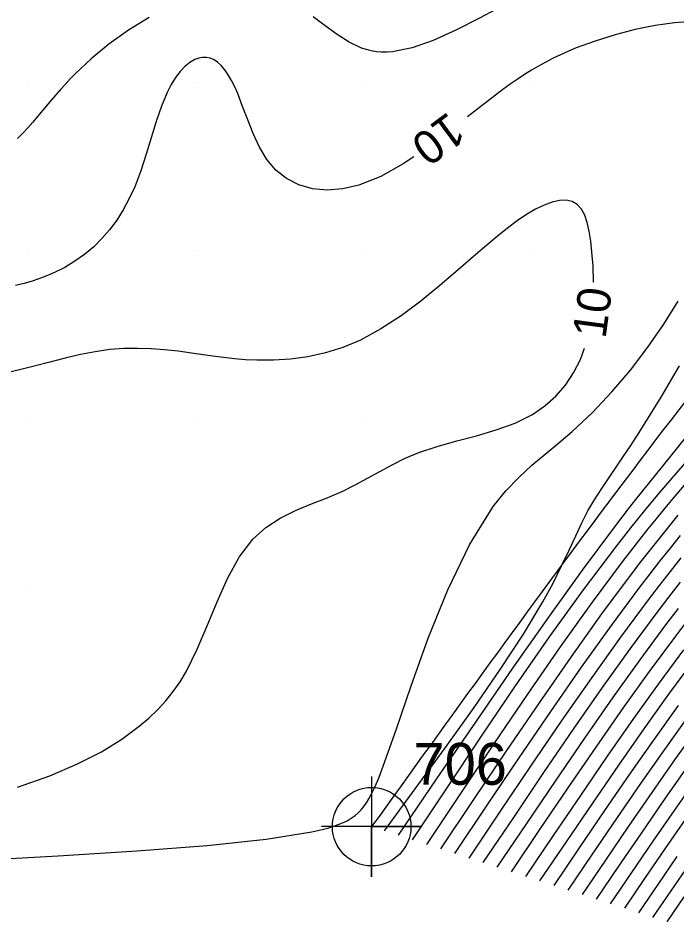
# Model space of a CAD drawing. Extents: x 2602990 to 2605851, y 618069 to 619180.
# Drawn here: x 2603719.5 to 2603758.8, y 618249.9 to 618303.9 of the extents above; entities that cross this region are included whole.
import ezdxf

# ---------------------------------------------------------------- set-up
doc = ezdxf.new("R2010")
doc.units = 0
for name, color, linetype in [('DTM Contours Major', 7, 'Continuous'), ('DTM Contours Major Text', 7, 'Continuous'), ('DTM Contours Minor', 7, 'Continuous'), ('DTM Contours Minor Text', 7, 'Continuous'), ('Exist DTM Breakline', 7, 'Continuous'), ('Exist DTM Breakline Cogo Number', 7, 'Continuous'), ('Exist DTM Breakline Cogo Point CELL', 7, 'Continuous'), ('Exist DTM QL2 LIDAR Elevation Point', 7, 'Continuous')]:
    doc.layers.add(name, color=color, linetype=linetype)

# ---------------------------------------------------------------- blocks, each defined once
blk = doc.blocks.new('EXIST DTM BREAKLINE COGO POINT')
at = {"layer": 'Exist DTM Breakline Cogo Point CELL'}
blk.add_lwpolyline([(0, 0.06), (0, -0.06), (0, 0), (0.06, 0), (-0.06, 0)], dxfattribs=at)
blk.add_circle((0, 0), 0.0469, dxfattribs=at)

msp = doc.modelspace()

# ---------------------------------------------------------------- linework, layer by layer
at = {"layer": 'DTM Contours Major'}
for points in [[(2603759.732, 618303.667), (2603758.66, 618303.592), (2603757.512, 618303.427), (2603756.32, 618303.182), (2603755.116, 618302.87), (2603753.933, 618302.5), (2603752.804, 618302.084), (2603752.329, 618301.887), (2603751.868, 618301.682), (2603751.42, 618301.468), (2603750.982, 618301.243), (2603750.552, 618301.007), (2603750.128, 618300.758), (2603749.703, 618300.492), (2603749.278, 618300.211), (2603748.852, 618299.916), (2603748.42, 618299.604), (2603747.981, 618299.276), (2603747.53, 618298.93), (2603746.308, 618297.971)], [(2603743.099, 618295.586), (2603742.455, 618295.156), (2603741.126, 618294.418), (2603739.815, 618293.891), (2603738.848, 618293.667), (2603737.917, 618293.598), (2603737.038, 618293.68), (2603736.225, 618293.908), (2603735.493, 618294.28), (2603734.855, 618294.792), (2603734.323, 618295.431), (2603733.88, 618296.169), (2603733.504, 618296.968), (2603733.176, 618297.79), (2603732.874, 618298.599), (2603732.578, 618299.357), (2603732.397, 618299.77), (2603732.209, 618300.149), (2603732.014, 618300.488), (2603731.811, 618300.786), (2603731.599, 618301.037), (2603731.376, 618301.238), (2603731.162, 618301.376), (2603730.941, 618301.469), (2603730.713, 618301.517), (2603730.481, 618301.521), (2603730.246, 618301.48), (2603730.01, 618301.394), (2603729.713, 618301.224), (2603729.42, 618300.987), (2603729.135, 618300.686), (2603728.861, 618300.324), (2603728.6, 618299.905), (2603728.357, 618299.43), (2603728.021, 618298.611), (2603727.714, 618297.703), (2603727.119, 618295.741), (2603726.793, 618294.748), (2603726.426, 618293.789), (2603726.103, 618293.088), (2603725.744, 618292.427), (2603725.352, 618291.807), (2603724.926, 618291.23), (2603724.467, 618290.697), (2603723.977, 618290.21), (2603723.433, 618289.753), (2603722.858, 618289.345), (2603722.255, 618288.984), (2603721.628, 618288.669), (2603720.977, 618288.398), (2603720.308, 618288.168), (2603719.815, 618288.027), (2603719.312, 618287.904)], [(2603716.836, 618253.558), (2603721.856, 618253.833), (2603726.546, 618254.132), (2603730.744, 618254.463), (2603734.284, 618254.839), (2603737.002, 618255.271), (2603737.371, 618255.351), (2603737.712, 618255.434), (2603738.028, 618255.519), (2603738.319, 618255.609), (2603738.587, 618255.703), (2603738.833, 618255.803), (2603738.976, 618255.868), (2603739.112, 618255.937), (2603739.241, 618256.008), (2603739.363, 618256.082), (2603739.479, 618256.16), (2603739.588, 618256.241), (2603739.779, 618256.404), (2603739.954, 618256.583), (2603740.116, 618256.78), (2603740.268, 618256.997), (2603740.414, 618257.236), (2603740.556, 618257.498), (2603740.672, 618257.732), (2603740.788, 618257.983), (2603740.905, 618258.254), (2603741.024, 618258.544), (2603741.272, 618259.187), (2603742.036, 618261.359), (2603742.933, 618263.981), (2603743.963, 618266.84), (2603745.124, 618269.723), (2603746.418, 618272.416), (2603747.843, 618274.706), (2603748.59, 618275.628), (2603749.363, 618276.435), (2603750.152, 618277.16), (2603750.953, 618277.836), (2603751.757, 618278.497), (2603752.557, 618279.177), (2603753.765, 618280.312), (2603754.933, 618281.545), (2603756.045, 618282.851), (2603757.085, 618284.207), (2603758.037, 618285.587), (2603758.885, 618286.967)], [(2603748.927, 618252.885), (2603750.631, 618255.411), (2603752.321, 618257.904), (2603753.985, 618260.331), (2603755.608, 618262.658), (2603757.177, 618264.854), (2603758.679, 618266.885), (2603759.469, 618267.917)], [(2603762.47, 618257.475), (2603761.761, 618256.5), (2603760.646, 618254.929), (2603759.544, 618253.346), (2603758.45, 618251.756), (2603757.361, 618250.163)]]:
    msp.add_lwpolyline(points, dxfattribs=at)
at = {"layer": 'DTM Contours Minor'}
for points in [[(2603749.955, 618305.441), (2603747.028, 618303.861), (2603745.615, 618303.141), (2603744.263, 618302.534), (2603742.992, 618302.089), (2603741.823, 618301.857), (2603741.492, 618301.836), (2603741.172, 618301.838), (2603740.861, 618301.864), (2603740.558, 618301.914), (2603740.263, 618301.986), (2603739.973, 618302.081), (2603739.237, 618302.431), (2603738.52, 618302.89), (2603737.807, 618303.413), (2603737.08, 618303.952)], [(2603727.281, 618303.9), (2603726.05, 618303.142), (2603724.889, 618302.308), (2603723.826, 618301.435), (2603722.888, 618300.559), (2603722.57, 618300.233), (2603722.271, 618299.911), (2603721.988, 618299.595), (2603721.459, 618298.979), (2603720.624, 618297.986), (2603720.334, 618297.65), (2603720.041, 618297.321), (2603719.741, 618296.999), (2603719.43, 618296.682)], [(2603753.835, 618288.103), (2603753.835, 618288.124), (2603753.803, 618289.048), (2603753.737, 618289.918), (2603753.666, 618290.556), (2603753.576, 618291.139), (2603753.457, 618291.657), (2603753.304, 618292.102), (2603753.108, 618292.466), (2603752.862, 618292.737), (2603752.559, 618292.912), (2603752.204, 618292.991), (2603751.802, 618292.979), (2603751.359, 618292.882), (2603750.88, 618292.705), (2603750.372, 618292.455), (2603749.836, 618292.135), (2603749.276, 618291.753), (2603748.691, 618291.316), (2603748.083, 618290.831), (2603747.451, 618290.304), (2603746.796, 618289.743), (2603745.746, 618288.832), (2603744.647, 618287.894), (2603743.507, 618286.968), (2603742.333, 618286.091), (2603741.132, 618285.303), (2603739.909, 618284.641), (2603738.862, 618284.203), (2603737.813, 618283.873), (2603736.768, 618283.642), (2603735.734, 618283.498), (2603734.718, 618283.432), (2603733.729, 618283.433), (2603733.052, 618283.468), (2603732.389, 618283.525), (2603731.736, 618283.599), (2603731.09, 618283.684), (2603729.808, 618283.866), (2603729.013, 618283.969), (2603728.214, 618284.056), (2603727.41, 618284.118), (2603726.599, 618284.146), (2603725.779, 618284.133), (2603724.949, 618284.07), (2603724.071, 618283.947), (2603723.179, 618283.773), (2603722.273, 618283.563), (2603721.353, 618283.328), (2603720.416, 618283.083), (2603719.463, 618282.839), (2603718.251, 618282.555)], [(2603719.425, 618257.932), (2603721.356, 618258.617), (2603723.015, 618259.326), (2603724.435, 618260.056), (2603725.649, 618260.806), (2603726.691, 618261.573), (2603727.271, 618262.064), (2603727.802, 618262.569), (2603728.287, 618263.095), (2603728.731, 618263.649), (2603729.141, 618264.239), (2603729.519, 618264.874), (2603730.161, 618266.175), (2603730.755, 618267.58), (2603731.342, 618269.014), (2603731.966, 618270.402), (2603732.666, 618271.67), (2603733.484, 618272.745), (2603734.263, 618273.441), (2603735.123, 618273.998), (2603736.038, 618274.455), (2603736.982, 618274.852), (2603737.93, 618275.227), (2603738.854, 618275.622), (2603739.603, 618275.993), (2603740.333, 618276.389), (2603741.061, 618276.797), (2603741.802, 618277.199), (2603742.572, 618277.58), (2603743.388, 618277.924), (2603744.492, 618278.292), (2603745.657, 618278.615), (2603746.845, 618278.93), (2603748.019, 618279.274), (2603749.143, 618279.685), (2603750.178, 618280.199), (2603750.918, 618280.704), (2603751.576, 618281.291), (2603752.152, 618281.952), (2603752.642, 618282.681), (2603753.045, 618283.47), (2603753.302, 618284.157)], [(2603741.337, 618255.335), (2603743.184, 618257.841), (2603744.985, 618260.308), (2603746.694, 618262.698), (2603748.265, 618264.97), (2603749.651, 618267.086), (2603750.807, 618269.007), (2603751.414, 618270.125), (2603751.928, 618271.151), (2603752.372, 618272.09), (2603752.767, 618272.948), (2603753.135, 618273.73), (2603753.498, 618274.44), (2603753.669, 618274.743), (2603753.844, 618275.036), (2603754.023, 618275.324), (2603754.401, 618275.897), (2603755.626, 618277.699), (2603756.012, 618278.279), (2603756.422, 618278.908), (2603756.859, 618279.591), (2603757.873, 618281.24), (2603758.967, 618283.092)], [(2603742.18, 618255.063), (2603744.501, 618258.472), (2603746.792, 618261.821), (2603749.021, 618265.049), (2603751.159, 618268.097), (2603753.175, 618270.903), (2603755.037, 618273.408), (2603755.927, 618274.563), (2603756.357, 618275.109), (2603757.533, 618276.576), (2603758.613, 618277.906), (2603759.574, 618279.104)], [(2603743.024, 618254.791), (2603745.08, 618257.901), (2603747.133, 618260.981), (2603749.177, 618263.998), (2603751.209, 618266.92), (2603753.224, 618269.717), (2603755.22, 618272.358), (2603756.058, 618273.422), (2603756.903, 618274.468), (2603757.765, 618275.509), (2603759.795, 618277.875)], [(2603743.867, 618254.518), (2603745.896, 618257.562), (2603747.913, 618260.568), (2603749.906, 618263.5), (2603751.863, 618266.319), (2603753.771, 618268.987), (2603755.62, 618271.469), (2603756.113, 618272.11), (2603756.603, 618272.738), (2603757.094, 618273.357), (2603757.589, 618273.971), (2603758.09, 618274.584), (2603758.6, 618275.2), (2603760.469, 618277.394)], [(2603744.711, 618254.246), (2603746.691, 618257.209), (2603748.658, 618260.133), (2603750.596, 618262.979), (2603752.491, 618265.708), (2603754.329, 618268.282), (2603756.096, 618270.661), (2603756.655, 618271.389), (2603757.209, 618272.098), (2603757.764, 618272.796), (2603758.323, 618273.487), (2603758.893, 618274.178)], [(2603745.554, 618253.974), (2603747.484, 618256.855), (2603749.399, 618259.696), (2603751.283, 618262.459), (2603753.12, 618265.104), (2603754.896, 618267.591), (2603756.595, 618269.882), (2603757.208, 618270.682), (2603757.815, 618271.458), (2603758.422, 618272.218), (2603759.035, 618272.971)], [(2603746.397, 618253.702), (2603748.274, 618256.497), (2603750.135, 618259.254), (2603751.965, 618261.934), (2603753.747, 618264.497), (2603755.466, 618266.906), (2603757.106, 618269.121), (2603757.768, 618269.985), (2603758.421, 618270.819), (2603759.074, 618271.634)], [(2603747.241, 618253.43), (2603749.062, 618256.137), (2603750.867, 618258.808), (2603752.642, 618261.404), (2603754.371, 618263.887), (2603756.037, 618266.222), (2603757.626, 618268.37), (2603758.333, 618269.293), (2603759.029, 618270.181)], [(2603748.084, 618253.157), (2603749.847, 618255.775), (2603751.596, 618258.357), (2603753.315, 618260.869), (2603754.991, 618263.274), (2603756.608, 618265.538), (2603758.151, 618267.626), (2603758.9, 618268.604)], [(2603759.209, 618266.147), (2603757.746, 618264.169), (2603756.223, 618262.04), (2603754.652, 618259.79), (2603753.045, 618257.448), (2603751.414, 618255.046), (2603749.771, 618252.613)], [(2603759.74, 618265.414), (2603758.315, 618263.487), (2603756.837, 618261.423), (2603755.317, 618259.248), (2603753.767, 618256.992), (2603752.196, 618254.68), (2603750.614, 618252.341)], [(2603758.885, 618262.808), (2603757.451, 618260.807), (2603755.983, 618258.708), (2603754.489, 618256.536), (2603752.977, 618254.314), (2603751.458, 618252.068)], [(2603759.454, 618262.123), (2603758.063, 618260.185), (2603756.645, 618258.162), (2603755.208, 618256.076), (2603753.758, 618253.946), (2603752.301, 618251.796)], [(2603760.025, 618261.443), (2603758.676, 618259.567), (2603757.309, 618257.619), (2603755.928, 618255.617), (2603754.538, 618253.58), (2603753.144, 618251.524)], [(2603759.291, 618258.95), (2603757.974, 618257.078), (2603756.649, 618255.16), (2603755.32, 618253.214), (2603753.988, 618251.252)], [(2603759.906, 618258.335), (2603758.639, 618256.538), (2603757.371, 618254.705), (2603756.101, 618252.848), (2603754.831, 618250.98)], [(2603759.306, 618255.999), (2603758.094, 618254.25), (2603756.884, 618252.483), (2603755.674, 618250.707)], [(2603758.818, 618253.797), (2603757.667, 618252.119), (2603756.518, 618250.435)], [(2603759.235, 618251.395), (2603758.205, 618249.891)]]:
    msp.add_lwpolyline(points, dxfattribs=at)
at = {"layer": 'Exist DTM Breakline'}
msp.add_spline([(2603751.583, 618450.596), (2603768.954, 618435.891), (2603805.072, 618414.752), (2603828.46, 618387.458), (2603819.191, 618359.408), (2603788.513, 618315.278), (2603769.845, 618293.995), (2603740.578, 618255.58)], degree=3, dxfattribs=at)
at = {"layer": 'Exist DTM QL2 LIDAR Elevation Point'}
for p, q in [((2603720, 618300), (2603720, 618300)), ((2603730, 618300), (2603730, 618300)), ((2603740, 618300), (2603740, 618300)), ((2603750, 618300), (2603750, 618300)), ((2603720, 618290), (2603720, 618290)), ((2603730, 618290), (2603730, 618290)), ((2603740, 618290), (2603740, 618290)), ((2603750, 618290), (2603750, 618290)), ((2603720, 618280), (2603720, 618280)), ((2603730, 618280), (2603730, 618280)), ((2603740, 618280), (2603740, 618280)), ((2603750, 618280), (2603750, 618280)), ((2603720, 618270), (2603720, 618270))]:
    msp.add_line(p, q, dxfattribs=at)

# ---------------------------------------------------------------- block references
at = {"layer": 'Exist DTM Breakline Cogo Point CELL', "xscale": 50, "yscale": 50}
msp.add_blockref('EXIST DTM BREAKLINE COGO POINT', (2603740.578, 618255.58), dxfattribs=at)

# ---------------------------------------------------------------- texts
at = {"layer": 'DTM Contours Major Text'}
msp.add_text('10', height=2, rotation=216.6146, dxfattribs=at).set_placement((2603745.175, 618298.322))
at = {"layer": 'DTM Contours Minor Text'}
msp.add_text('10', height=2, rotation=82.3133, dxfattribs=at).set_placement((2603754.547, 618284.685))
at = {"layer": 'Exist DTM Breakline Cogo Number'}
msp.add_text('706', height=2.5, dxfattribs=at).set_placement((2603743.078, 618258.08))

doc.saveas('drawing.dxf')
